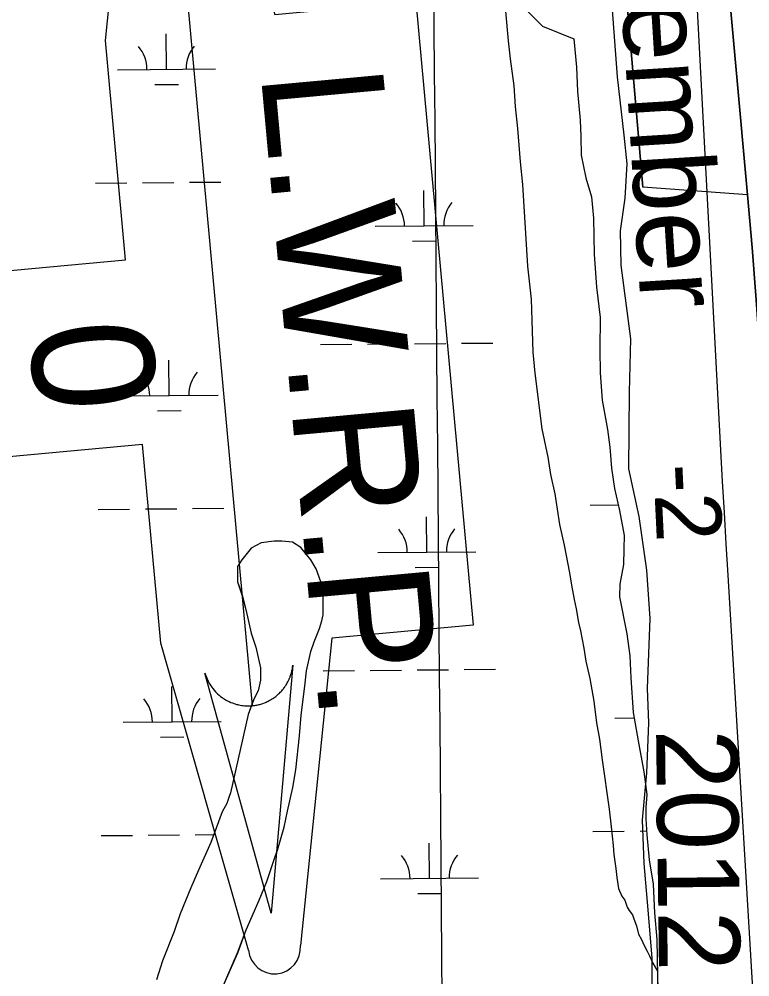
# Model space of a CAD drawing. Extents: x 3568792 to 3606828, y 529143 to 554785.
# Drawn here: x 3575924 to 3576670, y 534933 to 535909 of the extents above; entities that cross this region are included whole.
import ezdxf

# ---------------------------------------------------------------- set-up
doc = ezdxf.new("R2010")
doc.units = 0
for name, color, linetype in [('V-GRID-MAJR', 7, 'Continuous'), ('V-RIVR-EDGE', 7, 'Continuous'), ('V-RIVR-IDEN', 7, 'Continuous'), ('V-RIVR-RANG', 7, 'Continuous'), ('V-SITE-VEGE', 7, 'Continuous'), ('V-TOPO-DPTH', 7, 'Continuous'), ('V-TOPO-MINR', 7, 'Continuous'), ('V-TOPO-WATR', 7, 'Continuous'), ('V-TOPO-WATR-IDEN', 7, 'Continuous'), ('V-WETL-SWMP', 7, 'Continuous')]:
    doc.layers.add(name, color=color, linetype=linetype)

msp = doc.modelspace()

# ---------------------------------------------------------------- linework, layer by layer
at = {"layer": 'V-GRID-MAJR'}
msp.add_spline([(3576358.56, 534575.84), (3576309.21, 540634.72), (3576259.84, 546695.53), (3576210.47, 552756.36), (3576210.46, 552758.28)], degree=3, dxfattribs=at)
at = {"layer": 'V-RIVR-EDGE'}
for points in [[(3576525.95, 535959.99), (3576534.08, 535850.71), (3576541.14, 535791.26), (3576544.07, 535761.84), (3576542.18, 535727.02), (3576537.29, 535693.42), (3576537.81, 535658.6), (3576547.83, 535583.53), (3576546.49, 535528.91), (3576545.7, 535450.87), (3576556.39, 535402.21), (3576564.05, 535347.56), (3576567.53, 535298.33), (3576564.96, 535226.9), (3576566.07, 535192.07), (3576564.14, 535141.05), (3576559.82, 535093.04), (3576561.51, 535048.61), (3576565.6, 535001.17), (3576569.68, 534951.93)], [(3576569.68, 534951.93), (3576570.08, 534871.49), (3576567.54, 534813.87), (3576570.99, 534755.02), (3576577.91, 534640.35), (3576587.83, 534577.77)]]:
    msp.add_lwpolyline(points, dxfattribs=at)
at = {"layer": 'V-SITE-VEGE'}
for p, q in [((3576420.16, 535917.65), (3576423.05, 535887.42)), ((3576423.05, 535887.42), (3576425.19, 535869.02)), ((3576425.19, 535869.02), (3576428.71, 535841.43)), ((3576428.71, 535841.43), (3576430.21, 535820.4)), ((3576430.21, 535820.4), (3576432.38, 535798.06)), ((3576432.38, 535798.06), (3576435.31, 535763.89)), ((3576435.31, 535763.89), (3576437.48, 535740.89)), ((3576437.48, 535740.89), (3576442.82, 535657.41)), ((3576442.82, 535657.41), (3576446.4, 535623.9)), ((3576446.4, 535623.9), (3576447.24, 535602.21)), ((3576447.24, 535602.21), (3576448.18, 535569.99)), ((3576448.18, 535569.99), (3576450.34, 535548.31)), ((3576450.34, 535548.31), (3576457.41, 535491.81)), ((3576457.41, 535491.81), (3576463.58, 535462.93)), ((3576463.58, 535462.93), (3576466.37, 535445.2)), ((3576466.37, 535445.2), (3576470.49, 535425.5)), ((3576470.49, 535425.5), (3576475.37, 535393.98)), ((3576475.37, 535393.98), (3576480.15, 535372.97)), ((3576160.8, 535369.94), (3576151.43, 535358.21)), ((3576170.96, 535375.42), (3576160.8, 535369.94)), ((3576184.24, 535377), (3576170.96, 535375.42)), ((3576192.06, 535377), (3576184.24, 535377)), ((3576203, 535376.23), (3576192.06, 535377)), ((3576211.6, 535370.77), (3576203, 535376.23)), ((3576221.77, 535358.27), (3576211.6, 535370.77)), ((3576480.15, 535372.97), (3576485.66, 535344.74)), ((3576151.43, 535358.21), (3576146.75, 535351.18)), ((3576146.75, 535351.18), (3576146.76, 535335.55)), ((3576227.25, 535348.89), (3576221.77, 535358.27)), ((3576231.95, 535335.61), (3576227.25, 535348.89)), ((3576485.66, 535344.74), (3576487.74, 535332.27)), ((3576146.76, 535335.55), (3576151.46, 535322.26)), ((3576234.3, 535325.45), (3576231.95, 535335.61)), ((3576487.74, 535332.27), (3576490.5, 535317.82)), ((3576151.46, 535322.26), (3576155.38, 535307.42)), ((3576234.32, 535302), (3576234.3, 535325.45)), ((3576490.5, 535317.82), (3576492.56, 535307.98)), ((3576155.38, 535307.42), (3576160.87, 535283.19)), ((3576232.76, 535295.75), (3576234.32, 535302)), ((3576492.56, 535307.98), (3576494.65, 535294.18)), ((3576230.42, 535287.93), (3576232.76, 535295.75)), ((3576494.65, 535294.18), (3576496.7, 535285.65)), ((3576160.87, 535283.19), (3576165.56, 535269.12)), ((3576224.96, 535274.64), (3576230.42, 535287.93)), ((3576496.7, 535285.65), (3576500.14, 535267.93)), ((3576221.84, 535264.48), (3576224.96, 535274.64)), ((3576165.56, 535269.12), (3576170.27, 535248.03)), ((3576217.17, 535244.93), (3576221.84, 535264.48)), ((3576500.14, 535267.93), (3576502.23, 535254.79)), ((3576502.23, 535254.79), (3576506.33, 535237.07)), ((3576170.27, 535248.03), (3576170.28, 535235.52)), ((3576215.62, 535229.3), (3576217.17, 535244.93)), ((3576170.28, 535235.52), (3576167.94, 535224.58)), ((3576506.33, 535237.07), (3576510.48, 535214.09)), ((3576167.94, 535224.58), (3576163.26, 535215.2)), ((3576211.73, 535199.6), (3576215.62, 535229.3)), ((3576163.26, 535215.2), (3576157.8, 535200.34)), ((3576510.48, 535214.09), (3576513.3, 535191.75)), ((3576157.8, 535200.34), (3576139.88, 535120.61)), ((3576210.18, 535178.5), (3576211.73, 535199.6)), ((3576513.3, 535191.75), (3576516.08, 535175.34)), ((3576206.3, 535144.1), (3576210.18, 535178.5)), ((3576516.08, 535175.34), (3576518.89, 535154.32)), ((3576518.89, 535154.32), (3576525.91, 535103.74)), ((3576203.19, 535126.13), (3576206.3, 535144.1)), ((3576197.74, 535101.89), (3576203.19, 535126.13)), ((3576138.32, 535116.7), (3576135.98, 535109.66)), ((3576139.88, 535120.61), (3576138.32, 535116.7)), ((3576135.98, 535109.66), (3576131.3, 535101.06)), ((3576131.3, 535101.06), (3576125.06, 535084.64)), ((3576194.62, 535085.48), (3576197.74, 535101.89)), ((3576525.91, 535103.74), (3576528.04, 535086)), ((3576528.04, 535086), (3576530.17, 535066.95)), ((3576125.06, 535084.64), (3576119.6, 535069.79)), ((3576187.6, 535062.02), (3576194.62, 535085.48)), ((3576119.6, 535069.79), (3576107.12, 535041.64)), ((3576530.17, 535066.95), (3576530.91, 535057.75)), ((3576185.26, 535055.77), (3576187.6, 535062.02)), ((3576530.91, 535057.75), (3576533.01, 535043.3)), ((3576176.69, 535029.97), (3576185.26, 535055.77)), ((3576107.12, 535041.64), (3576099.31, 535023.66)), ((3576533.01, 535043.3), (3576533.75, 535034.09)), ((3576168.88, 535011.21), (3576176.69, 535029.97)), ((3576533.75, 535034.09), (3576535.72, 535023.14)), ((3576099.31, 535023.66), (3576088.39, 534997.08)), ((3576535.72, 535023.14), (3576538.93, 535015.12)), ((3576155.62, 534980.72), (3576168.88, 535011.21)), ((3576538.93, 535015.12), (3576542.14, 535011.09)), ((3576542.14, 535011.09), (3576544.55, 535003.87)), ((3576544.55, 535003.87), (3576546.54, 535000.67)), ((3576546.54, 535000.67), (3576549.87, 534996.09)), ((3576088.39, 534997.08), (3576082.15, 534979.1)), ((3576549.87, 534996.09), (3576551.21, 534992.16)), ((3576551.21, 534992.16), (3576553.91, 534984.95)), ((3576082.15, 534979.1), (3576070.45, 534949.39)), ((3576147.04, 534957.26), (3576155.62, 534980.72)), ((3576553.91, 534984.95), (3576555.96, 534976.42)), ((3576555.96, 534976.42), (3576559.1, 534971.03)), ((3576559.1, 534971.03), (3576561.92, 534965.01)), ((3576561.92, 534965.01), (3576564.73, 534958.98)), ((3576564.73, 534958.98), (3576567.33, 534954.16)), ((3576070.45, 534949.39), (3576064.21, 534929.84)), ((3576130.66, 534919.73), (3576147.04, 534957.26)), ((3576567.33, 534954.16), (3576570.55, 534946.93)), ((3576570.55, 534946.93), (3576575.29, 534938.57)), ((3576575.29, 534938.57), (3576575.73, 534915.66))]:
    msp.add_line(p, q, dxfattribs=at)
at = {"layer": 'V-TOPO-DPTH'}
for points in [[(3576667.28, 535730.27), (3576560.33, 535737.98), (3576517.88, 536232.75), (3576516.59, 536246.7), (3576515.18, 536260.63), (3576513.58, 536274.55), (3576511.86, 536288.45), (3576432.78, 536895.31), (3576430.5, 536911.94), (3576428.09, 536928.55), (3576425.46, 536945.13), (3576422.7, 536961.69), (3576417.69, 536990.54), (3576416.89, 536994.76), (3576416.43, 536996.85), (3576415.95, 536998.94), (3576414.9, 537003.28), (3576413.79, 537007.51), (3576412.56, 537011.7), (3576411.15, 537015.84), (3576409.63, 537019.94), (3576400.6, 537042.84), (3576398.84, 537046.86), (3576493.5, 537061.75)], [(3576493.5, 537061.75), (3576495.89, 537051.17), (3576500.13, 537031.82), (3576504.21, 537012.43), (3576508.06, 536993), (3576511.74, 536973.53), (3576515.21, 536954.03), (3576518.55, 536934.5), (3576521.7, 536914.94), (3576524.73, 536895.36), (3576613.4, 536302.34), (3576615.56, 536286.94), (3576617.55, 536271.52), (3576619.27, 536256.06), (3576620.82, 536240.58), (3576667.28, 535730.27)], [(3576744.26, 534579.09), (3576721.79, 534896.58), (3576715.91, 534981.85), (3576710.24, 535067.13), (3576704.87, 535152.44), (3576699.71, 535237.76), (3576694.55, 535325.74), (3576692.12, 535367.08), (3576689.69, 535408.41), (3576687.26, 535449.75), (3576684.82, 535491.08), (3576683.36, 535515.78), (3576679.94, 535569.45), (3576676.18, 535623.09), (3576671.9, 535676.69), (3576667.28, 535730.27), (3576620.82, 536240.58)]]:
    msp.add_lwpolyline(points, dxfattribs=at)
at = {"layer": 'V-TOPO-MINR'}
for points in [[(3576620.82, 536240.58), (3576667.28, 535730.27), (3576671.9, 535676.69), (3576676.18, 535623.09), (3576679.94, 535569.45), (3576683.36, 535515.78), (3576684.82, 535491.08), (3576687.26, 535449.75), (3576689.69, 535408.41), (3576692.12, 535367.08), (3576694.55, 535325.74), (3576699.71, 535237.76), (3576704.87, 535152.44), (3576710.24, 535067.13), (3576715.91, 534981.85), (3576721.79, 534896.58), (3576744.26, 534579.09)], [(3576607.17, 536086.22), (3576639.77, 535469.98), (3576641.49, 535438.13), (3576643.26, 535406.28), (3576645.09, 535374.43), (3576646.97, 535342.59), (3576690.13, 534624.33)]]:
    msp.add_lwpolyline(points, dxfattribs=at)
at = {"layer": 'V-TOPO-WATR'}
msp.add_lwpolyline([(3576398.84, 537046.86), (3576400.6, 537042.84), (3576409.63, 537019.94), (3576411.15, 537015.84), (3576412.56, 537011.7), (3576413.79, 537007.51), (3576414.9, 537003.28), (3576415.95, 536998.94), (3576416.43, 536996.85), (3576416.89, 536994.76), (3576417.69, 536990.54), (3576422.7, 536961.69), (3576425.46, 536945.13), (3576428.09, 536928.55), (3576430.5, 536911.94), (3576432.78, 536895.31), (3576511.86, 536288.45), (3576513.58, 536274.55), (3576515.18, 536260.63), (3576516.59, 536246.7), (3576517.88, 536232.75), (3576560.33, 535737.98)], dxfattribs=at)
at = {"layer": 'V-TOPO-WATR-IDEN'}
msp.add_line((3576093.26, 535957.46), (3576161.93, 535209.4), dxfattribs=at)
for points in [[(3576158.2, 534960.05), (3576068.52, 535273.01), (3576049.92, 535475.58), (3575895.24, 535461.38), (3575877.96, 535649.66), (3576032.64, 535663.86), (3576012.09, 535887.75), (3576044.2, 536201.97)], [(3576097, 536206.82), (3576184.81, 535914.25), (3576328.92, 535927.48), (3576387.29, 535291.62), (3576243.17, 535278.4), (3576211, 534964.89)]]:
    msp.add_lwpolyline(points, dxfattribs=at)
msp.add_lwpolyline([(3576203.31, 535250.86), (3576181.35, 534997.89), (3576113.69, 535242.64), (3576115.14, 535238.31), (3576116.94, 535234.28), (3576117.77, 535232.71), (3576118.55, 535231.36), (3576119.57, 535229.76), (3576120.61, 535228.25), (3576121.55, 535226.98), (3576122.92, 535225.3), (3576124.48, 535223.56), (3576125.38, 535222.63), (3576126.59, 535221.46), (3576128.25, 535219.99), (3576129.58, 535218.91), (3576131.07, 535217.8), (3576132.07, 535217.1), (3576133.19, 535216.36), (3576134.59, 535215.51), (3576135.9, 535214.77), (3576137.23, 535214.07), (3576138.34, 535213.53), (3576140.01, 535212.79), (3576141.64, 535212.14), (3576142.97, 535211.67), (3576144.54, 535211.16), (3576145.91, 535210.77), (3576147.15, 535210.46), (3576148.11, 535210.24), (3576149.59, 535209.95), (3576151.12, 535209.7), (3576152.57, 535209.51), (3576154.05, 535209.36), (3576155.43, 535209.27), (3576156.94, 535209.22), (3576158.18, 535209.22), (3576159.96, 535209.27), (3576161.93, 535209.4), (3576162.56, 535209.47), (3576163.48, 535209.57), (3576164.57, 535209.73), (3576165.62, 535209.9), (3576166.64, 535210.09), (3576167.63, 535210.29), (3576168.79, 535210.56), (3576169.59, 535210.77), (3576170.76, 535211.1), (3576171.85, 535211.44), (3576172.59, 535211.69), (3576174.48, 535212.38), (3576175.48, 535212.79), (3576176.16, 535213.08), (3576177.28, 535213.59), (3576178.26, 535214.07), (3576179.27, 535214.59), (3576180.45, 535215.25), (3576181.54, 535215.89), (3576182.37, 535216.41), (3576183.08, 535216.87), (3576184.02, 535217.51), (3576184.86, 535218.11), (3576185.81, 535218.83), (3576186.75, 535219.58), (3576187.69, 535220.37), (3576188.85, 535221.41), (3576189.65, 535222.17), (3576190.52, 535223.04), (3576191.35, 535223.91), (3576192, 535224.63), (3576192.69, 535225.43), (3576193.68, 535226.65), (3576193.72, 535226.7), (3576194.29, 535227.44), (3576194.7, 535227.99), (3576195.3, 535228.83), (3576196.02, 535229.9), (3576196.57, 535230.76), (3576197.05, 535231.55), (3576197.64, 535232.57), (3576198.19, 535233.57), (3576198.56, 535234.29), (3576199.03, 535235.24), (3576199.64, 535236.57), (3576199.98, 535237.37), (3576200.23, 535238), (3576200.46, 535238.58), (3576200.72, 535239.28), (3576201.05, 535240.2), (3576201.36, 535241.13), (3576201.64, 535242.06), (3576201.91, 535242.99), (3576202.21, 535244.2), (3576202.38, 535244.92), (3576202.63, 535246.09), (3576202.88, 535247.45), (3576203.04, 535248.48), (3576203.14, 535249.25), (3576203.23, 535249.97), (3576203.28, 535250.49)], close=True, dxfattribs=at)
msp.add_arc((3576184.6, 534962.47), 26.51, 185.24463, 5.24463, dxfattribs=at)
at = {"layer": 'V-WETL-SWMP'}
for p, q in [((3576422.18, 535938.14), (3576452.91, 535907.42)), ((3576452.91, 535907.42), (3576458.03, 535902.3)), ((3576458.03, 535902.3), (3576490.03, 535889.41)), ((3576074.46, 535858.29), (3576074.16, 535894.29)), ((3576490.03, 535889.41), (3576492.8, 535860.48)), ((3576024.47, 535857.87), (3576124.46, 535858.71)), ((3576492.8, 535860.48), (3576493.83, 535835.78)), ((3576062.59, 535842.76), (3576086.59, 535842.96)), ((3576493.83, 535835.78), (3576496.35, 535806.35)), ((3576496.35, 535806.35), (3576497.11, 535789.89)), ((3576497.11, 535789.89), (3576497.63, 535770.68)), ((3576497.63, 535770.68), (3576502.39, 535747.74)), ((3576002.03, 535742.25), (3576034.03, 535742.52)), ((3576050.03, 535742.65), (3576082.03, 535742.92)), ((3576098.03, 535743.06), (3576130.03, 535743.33)), ((3576502.39, 535747.74), (3576507.89, 535728.29)), ((3576337.25, 535698.64), (3576336.95, 535734.64)), ((3576507.89, 535728.29), (3576509.91, 535706.59)), ((3576509.91, 535706.59), (3576510.69, 535669.67)), ((3576287.26, 535698.22), (3576387.25, 535699.06)), ((3576325.38, 535683.11), (3576349.38, 535683.31)), ((3576510.69, 535669.67), (3576513.22, 535636.25)), ((3576513.22, 535636.25), (3576516.74, 535605.07)), ((3576516.74, 535605.07), (3576516.52, 535572.64)), ((3576231.43, 535577.67), (3576263.43, 535577.94)), ((3576279.43, 535578.08), (3576311.42, 535578.35)), ((3576327.42, 535578.48), (3576359.42, 535578.75)), ((3576375.42, 535578.89), (3576407.42, 535579.16)), ((3576516.52, 535572.64), (3576516.79, 535548.7)), ((3576077.27, 535525.63), (3576076.97, 535561.63)), ((3576516.79, 535548.7), (3576518.81, 535520.76)), ((3576027.27, 535525.21), (3576127.27, 535526.05)), ((3576518.81, 535520.76), (3576524.32, 535491.08)), ((3576065.4, 535510.1), (3576089.4, 535510.3)), ((3576524.32, 535491.08), (3576526.84, 535472.87)), ((3576526.84, 535472.87), (3576528.6, 535451.42)), ((3576528.6, 535451.42), (3576531.61, 535430.97)), ((3576531.61, 535430.97), (3576536.62, 535408.53)), ((3576004.84, 535409.58), (3576036.84, 535409.85)), ((3576052.84, 535409.99), (3576084.84, 535410.26)), ((3576100.84, 535410.39), (3576132.84, 535410.66)), ((3576506.73, 535413.82), (3576535.39, 535414.06)), ((3576536.62, 535408.53), (3576541.39, 535383.09)), ((3576340.06, 535365.98), (3576339.76, 535401.98)), ((3576541.39, 535383.09), (3576540.9, 535369.37)), ((3576160.79, 535369.94), (3576151.42, 535358.21)), ((3576170.94, 535375.42), (3576160.79, 535369.94)), ((3576184.23, 535376.99), (3576170.94, 535375.42)), ((3576192.05, 535377), (3576184.23, 535376.99)), ((3576202.99, 535376.23), (3576192.05, 535377)), ((3576211.59, 535370.76), (3576202.99, 535376.23)), ((3576221.76, 535358.26), (3576211.59, 535370.76)), ((3576540.9, 535369.37), (3576540.66, 535353.4)), ((3576290.06, 535365.56), (3576390.06, 535366.4)), ((3576151.42, 535358.21), (3576146.73, 535351.18)), ((3576146.73, 535351.18), (3576146.75, 535335.54)), ((3576227.24, 535348.89), (3576221.76, 535358.26)), ((3576328.19, 535350.45), (3576352.19, 535350.65)), ((3576540.66, 535353.4), (3576536.94, 535333.19)), ((3576231.94, 535335.61), (3576227.24, 535348.89)), ((3576146.75, 535335.54), (3576151.45, 535322.26)), ((3576234.29, 535325.45), (3576231.94, 535335.61)), ((3576536.94, 535333.19), (3576536.45, 535320.47)), ((3576151.45, 535322.26), (3576155.36, 535307.41)), ((3576234.31, 535302), (3576234.29, 535325.45)), ((3576536.45, 535320.47), (3576544.22, 535282.81)), ((3576155.36, 535307.41), (3576160.85, 535283.19)), ((3576232.75, 535295.75), (3576234.31, 535302)), ((3576230.41, 535287.93), (3576232.75, 535295.75)), ((3576160.85, 535283.19), (3576165.55, 535269.12)), ((3576224.95, 535274.64), (3576230.41, 535287.93)), ((3576544.22, 535282.81), (3576547.24, 535260.12)), ((3576221.83, 535264.48), (3576224.95, 535274.64)), ((3576165.55, 535269.12), (3576170.26, 535248.02)), ((3576217.16, 535244.93), (3576221.83, 535264.48)), ((3576547.24, 535260.12), (3576548, 535237.67)), ((3576170.26, 535248.02), (3576170.27, 535235.52)), ((3576215.6, 535229.3), (3576217.16, 535244.93)), ((3576234.24, 535245.01), (3576266.23, 535245.28)), ((3576282.23, 535245.42), (3576314.23, 535245.69)), ((3576330.23, 535245.82), (3576362.23, 535246.09)), ((3576378.23, 535246.23), (3576410.23, 535246.5)), ((3576170.27, 535235.52), (3576167.93, 535224.58)), ((3576548, 535237.67), (3576550.53, 535202.5)), ((3576080.08, 535192.97), (3576079.78, 535228.97)), ((3576167.93, 535224.58), (3576163.25, 535215.19)), ((3576211.72, 535199.6), (3576215.6, 535229.3)), ((3576163.25, 535215.19), (3576157.79, 535200.34)), ((3576030.08, 535192.54), (3576130.08, 535193.39)), ((3576157.79, 535200.34), (3576139.87, 535120.61)), ((3576210.17, 535178.49), (3576211.72, 535199.6)), ((3576531.97, 535196.78), (3576551.49, 535196.94)), ((3576550.53, 535202.5), (3576555.55, 535173.57)), ((3576068.21, 535177.43), (3576092.21, 535177.64)), ((3576206.29, 535144.1), (3576210.17, 535178.49)), ((3576555.55, 535173.57), (3576561.31, 535141.89)), ((3576203.18, 535126.12), (3576206.29, 535144.1)), ((3576561.31, 535141.89), (3576564.58, 535118.7)), ((3576197.72, 535101.89), (3576203.18, 535126.12)), ((3576138.31, 535116.7), (3576135.97, 535109.66)), ((3576139.87, 535120.61), (3576138.31, 535116.7)), ((3576564.58, 535118.7), (3576563.59, 535105.73)), ((3576135.97, 535109.66), (3576131.29, 535101.06)), ((3576563.59, 535105.73), (3576563.6, 535094)), ((3576131.29, 535101.06), (3576125.05, 535084.64)), ((3576194.61, 535085.48), (3576197.72, 535101.89)), ((3576563.6, 535094), (3576564.61, 535077.79)), ((3576007.65, 535076.92), (3576039.65, 535077.19)), ((3576055.65, 535077.32), (3576087.65, 535077.59)), ((3576103.64, 535077.73), (3576122.57, 535077.89)), ((3576125.05, 535084.64), (3576119.59, 535069.79)), ((3576187.59, 535062.02), (3576194.61, 535085.48)), ((3576509.53, 535081.15), (3576541.53, 535081.42)), ((3576557.53, 535081.56), (3576564.38, 535081.62)), ((3576564.61, 535077.79), (3576566.88, 535052.35)), ((3576119.59, 535069.79), (3576107.11, 535041.64)), ((3576342.87, 535033.32), (3576342.57, 535069.31)), ((3576185.25, 535055.77), (3576187.59, 535062.02)), ((3576176.68, 535029.97), (3576185.25, 535055.77)), ((3576566.88, 535052.35), (3576570.9, 535027.41)), ((3576107.11, 535041.64), (3576099.31, 535023.66)), ((3576168.87, 535011.21), (3576176.68, 535029.97)), ((3576292.87, 535032.89), (3576392.87, 535033.74)), ((3576570.9, 535027.41), (3576572.42, 534998.22)), ((3576099.31, 535023.66), (3576088.38, 534997.08)), ((3576331, 535017.78), (3576355, 535017.99)), ((3576155.61, 534980.71), (3576168.87, 535011.21)), ((3576572.42, 534998.22), (3576574.69, 534971.04)), ((3576088.38, 534997.08), (3576082.15, 534979.1)), ((3576082.15, 534979.1), (3576070.44, 534949.39)), ((3576147.03, 534957.26), (3576155.61, 534980.71)), ((3576574.69, 534971.04), (3576575.74, 534915.66)), ((3576070.44, 534949.39), (3576064.21, 534929.84)), ((3576130.65, 534919.73), (3576147.03, 534957.26))]:
    msp.add_line(p, q, dxfattribs=at)
for centre, start, end in [((3576019.22, 535858.3), 359.71152, 41.25518), ((3576129.7, 535859.23), 139.71153, 181.25519), ((3576282.01, 535698.65), 359.71152, 41.25518), ((3576392.49, 535699.58), 139.71153, 181.25519), ((3576022.03, 535525.64), 359.71152, 41.25518), ((3576132.51, 535526.57), 139.71153, 181.25519), ((3576284.82, 535365.99), 359.71152, 41.25518), ((3576395.3, 535366.92), 139.71153, 181.25519), ((3576024.83, 535192.98), 359.71152, 41.25518), ((3576135.32, 535193.91), 139.71153, 181.25519), ((3576398.11, 535034.26), 139.71153, 181.25519), ((3576287.62, 535033.32), 359.71152, 41.25518)]:
    msp.add_arc(centre, 35.25, start, end, dxfattribs=at)

# ---------------------------------------------------------------- texts
at = {"layer": 'V-RIVR-IDEN'}
for s, rotation, p in [('September', 273.5655, (3576524.67, 536154.23)), ('2012', 270.69668, (3576573.91, 535185.07))]:
    msp.add_text(s, height=83, rotation=rotation, dxfattribs=at).set_placement(p)
at = {"layer": 'V-RIVR-RANG'}
msp.add_text('-2', height=67, rotation=272.77178, dxfattribs=at).set_placement((3576571, 535454.89))
at = {"layer": 'V-TOPO-WATR-IDEN'}
for s, height, rotation, p in [('L.W.R.P.', 124.499, 275.24457, (3576170.46, 535854.94)), ('0', 124.5, 275.24467, (3575933.56, 535596.81))]:
    msp.add_text(s, height=height, rotation=rotation, dxfattribs=at).set_placement(p)

doc.saveas('drawing.dxf')
